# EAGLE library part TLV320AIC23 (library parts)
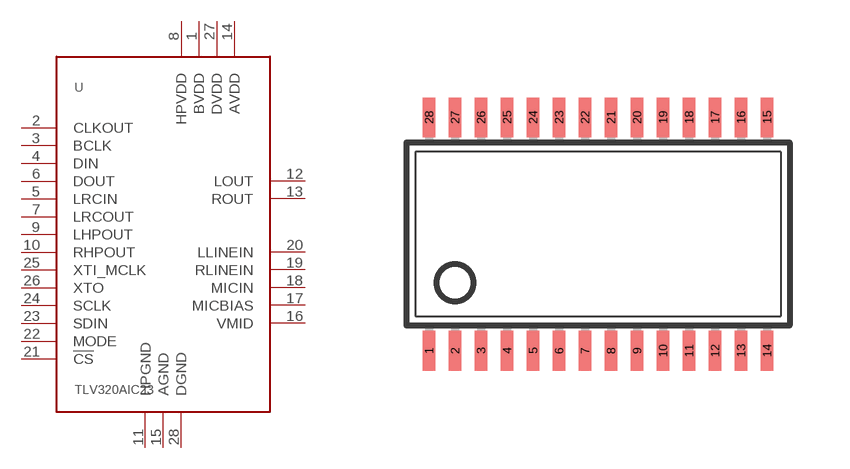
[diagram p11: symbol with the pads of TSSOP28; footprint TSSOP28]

Designator prefix -

## TLV320AIC23  [TSSOP28]
1  BVDD
2  CLKOUT
3  BCLK
4  DIN
5  LRCIN
6  DOUT
7  LRCOUT
8  HPVDD
9  LHPOUT
10  RHPOUT
11  HPGND
12  LOUT
13  ROUT
14  AVDD
15  AGND
16  VMID
17  MICBIAS
18  MICIN
19  RLINEIN
20  LLINEIN
21  !CS
22  MODE
23  SDIN
24  SCLK
25  XTI_MCLK
26  XTO
27  DVDD
28  DGND

## Footprint TSSOP28 (pad centres in mm)
Thin Shrink Small Outline Plastic 28 MAX3223-MAX3243.pdf
smd 0.305 x 0.991: 1 -4.225,-2.918; 2 -3.575,-2.918; 3 -2.925,-2.918; 4 -2.275,-2.918; 5 -1.625,-2.918; 6 -0.975,-2.918; 7 -0.325,-2.918; 8 0.325,-2.918; 9 0.975,-2.918; 10 1.625,-2.918; 11 2.275,-2.918; 12 2.925,-2.918; 13 3.575,-2.918; 14 4.225,-2.918; 15 4.225,2.918; 16 3.575,2.918; 17 2.925,2.918; 18 2.275,2.918; 19 1.625,2.918; 20 0.975,2.918; 21 0.325,2.918; 22 -0.325,2.918; 23 -0.975,2.918; 24 -1.625,2.918; 25 -2.275,2.918; 26 -2.925,2.918; 27 -3.575,2.918; 28 -4.225,2.918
